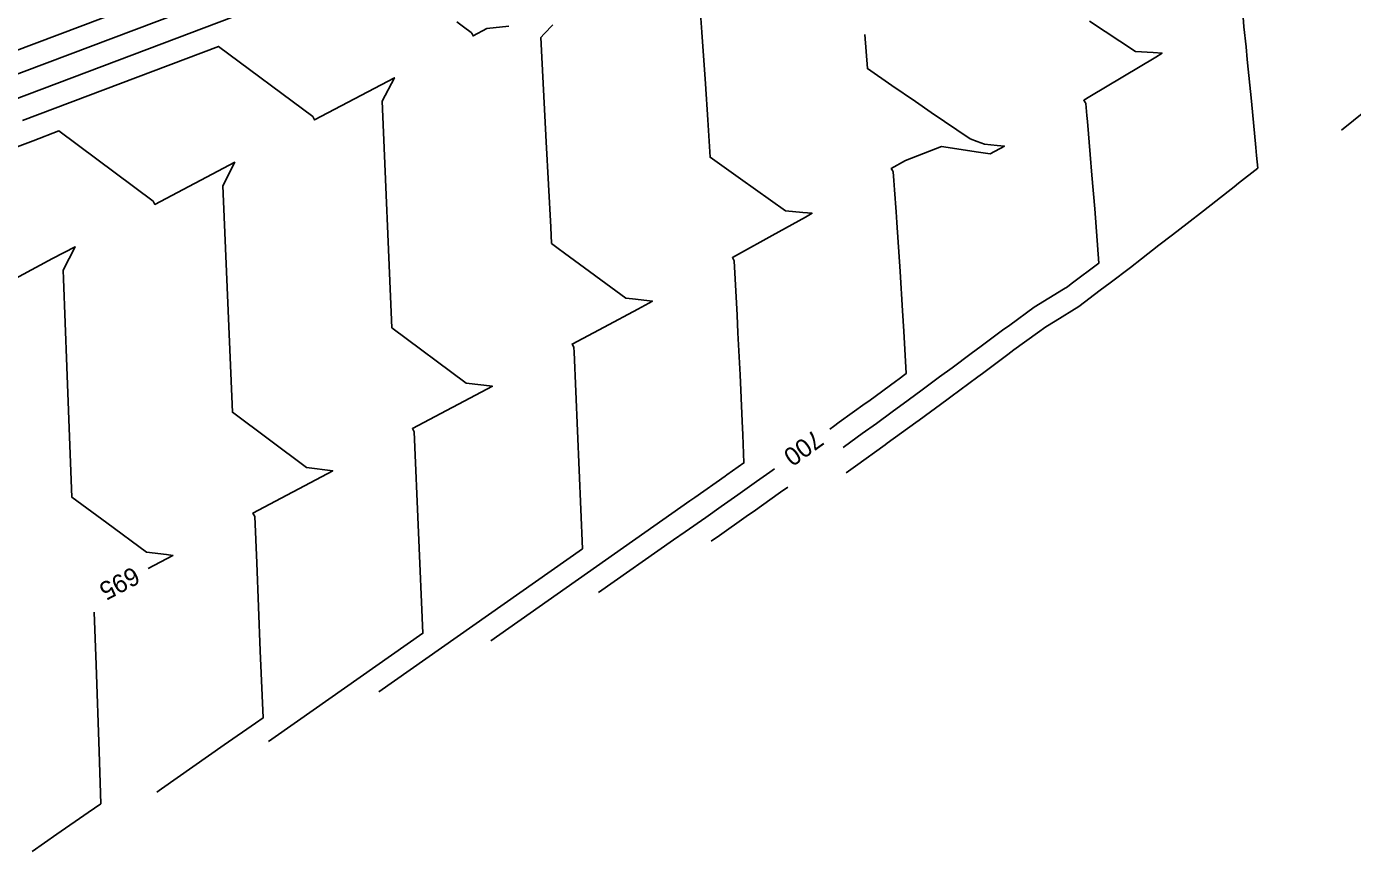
# Model space of a CAD drawing. Extents: x 1487507 to 1489130, y 497211 to 499439.
# Drawn here: x 1488049 to 1488223.8, y 498457.6 to 498566.4 of the extents above; entities that cross this region are included whole.
import ezdxf

# ---------------------------------------------------------------- set-up
doc = ezdxf.new("R2010")
doc.units = 0
for name, color, linetype in [('Prop CMT Ditch DDE', 7, 'Continuous'), ('Prop Drainage Ditch Flow Line', 7, 'Continuous'), ('Prop Drainage Structure Pipe Outlet Channel Detail CELL', 7, 'Continuous')]:
    doc.layers.add(name, color=color, linetype=linetype)

msp = doc.modelspace()

# ---------------------------------------------------------------- linework, layer by layer
at = {"layer": 'Prop CMT Ditch DDE'}
for points in [[(1488022.19, 498550.42), (1488026.78, 498552.19), (1488031.49, 498553.98), (1488036.2, 498555.77), (1488040.91, 498557.55), (1488045.62, 498559.34), (1488092.76, 498577.16), (1488093.19, 498577.32), (1488097.35, 498578.88), (1488097.69, 498579.01), (1488097.79, 498579.05)], [(1488094.17, 498574.51), (1488047.03, 498556.69)], [(1488137.54, 498572.49), (1488138.03, 498565.7), (1488138.48, 498558.89), (1488138.81, 498554.11), (1488139.11, 498549.2), (1488143.12, 498546.34), (1488149.05, 498542.14), (1488151.35, 498541.91), (1488152.54, 498541.8), (1488151.68, 498541.31), (1488147.27, 498538.86), (1488142.86, 498536.42), (1488142.04, 498535.97), (1488142.09, 498535.89), (1488142.28, 498535.53), (1488142.37, 498533.91), (1488142.41, 498533.14), (1488142.67, 498528.35), (1488142.78, 498526.04), (1488143.07, 498520.49), (1488143.33, 498514.39), (1488143.41, 498512.61), (1488143.56, 498508.89), (1488141.33, 498507.31), (1488141.11, 498507.16), (1488137.1, 498504.33), (1488136.45, 498503.87), (1488132.88, 498501.38), (1488110.17, 498485.43)], [(1488095.43, 498478.71), (1488122.27, 498497.56), (1488121.17, 498523.5), (1488121.14, 498524.12), (1488121.13, 498524.15), (1488120.91, 498524.56), (1488125.12, 498526.8), (1488129.57, 498529.18), (1488131.5, 498530.22), (1488128.85, 498530.52), (1488128.01, 498530.62), (1488119.92, 498536.56), (1488119.07, 498537.18), (1488118.19, 498537.84), (1488118.09, 498539.99), (1488117.5, 498551.24), (1488116.97, 498561.53), (1488116.78, 498564.97), (1488117.22, 498565.45), (1488118.37, 498566.67)], [(1488112.57, 498566.49), (1488109.68, 498566.18), (1488107.85, 498565.2), (1488107.72, 498565.45), (1488107.62, 498565.64), (1488106.6, 498566.4), (1488105.71, 498567.07)], [(1488189.12, 498567.13), (1488195.19, 498563.14), (1488197.51, 498563), (1488198.7, 498562.92), (1488197.86, 498562.41), (1488193.52, 498559.8), (1488189.18, 498557.2), (1488188.37, 498556.72), (1488188.58, 498556.37), (1488188.63, 498556.29), (1488188.77, 498554.68), (1488188.84, 498553.9), (1488189.22, 498549.55), (1488189.44, 498546.83), (1488189.81, 498542.39), (1488190.36, 498535.24), (1488190.34, 498535.23), (1488186.69, 498532.48), (1488186.22, 498532.11), (1488185.69, 498531.79), (1488181.85, 498529.42), (1488178.61, 498527.07), (1488177.67, 498526.39), (1488174.83, 498524.27), (1488173.53, 498523.3), (1488171, 498521.43), (1488169.37, 498520.22), (1488167.08, 498518.53), (1488165.2, 498517.16), (1488163.12, 498515.64), (1488161.02, 498514.1), (1488159.16, 498512.76), (1488156.82, 498511.06), (1488156.64, 498510.93)], [(1488209.37, 498567.65), (1488209.49, 498566.4), (1488209.77, 498563.76), (1488209.93, 498562.1), (1488210.48, 498556.61), (1488211.06, 498550.48), (1488211.16, 498549.44), (1488211.31, 498547.77), (1488208.77, 498545.76), (1488208.2, 498545.31), (1488207.39, 498544.68), (1488204.14, 498542.13), (1488201.99, 498540.46), (1488200.05, 498538.95), (1488198.28, 498537.58), (1488195.96, 498535.79), (1488194.51, 498534.67), (1488191.86, 498532.64), (1488190.55, 498531.65), (1488187.73, 498529.52), (1488184.62, 498527.6), (1488183.35, 498526.82), (1488182.28, 498526.04), (1488179.16, 498523.79), (1488178.36, 498523.19), (1488175.01, 498520.69), (1488174.39, 498520.24), (1488170.84, 498517.61), (1488170.31, 498517.21), (1488166.67, 498514.54), (1488166.24, 498514.22), (1488162.47, 498511.48), (1488162.19, 498511.27), (1488158.27, 498508.44), (1488157.06, 498507.56)], [(1488048.43, 498554.03), (1488074.27, 498563.81), (1488086.71, 498554.55), (1488086.95, 498554.11), (1488097.47, 498559.68), (1488095.88, 498556.57), (1488097.15, 498526.7), (1488106.92, 498519.42), (1488110.39, 498518.99), (1488099.86, 498513.42), (1488100.1, 498512.98), (1488101.23, 498486.42), (1488088.83, 498477.72), (1488084.7, 498474.82), (1488080.89, 498472.15)], [(1488222.36, 498552.77), (1488225.52, 498555.31)], [(1488030.68, 498544.12), (1488030.99, 498544.24), (1488035.7, 498546.03), (1488040.41, 498547.81), (1488045.12, 498549.6), (1488049.84, 498551.38), (1488053.23, 498552.67), (1488065.67, 498543.41), (1488065.91, 498542.97), (1488076.43, 498548.54), (1488074.84, 498545.44), (1488076.11, 498515.56), (1488085.88, 498508.29), (1488089.34, 498507.86), (1488078.82, 498502.28), (1488079.06, 498501.84), (1488079.32, 498495.69), (1488079.8, 498484.09), (1488080.16, 498475.27), (1488079.18, 498474.58), (1488075.05, 498471.69), (1488070.92, 498468.8), (1488066.79, 498465.92), (1488066.14, 498465.47)], [(1488149.33, 498505.69), (1488148.4, 498505.03), (1488144.76, 498502.44), (1488144.17, 498502.03), (1488140.02, 498499.11), (1488139.93, 498499.04), (1488139.25, 498498.56)]]:
    msp.add_lwpolyline(points, dxfattribs=at)
at = {"layer": 'Prop Drainage Ditch Flow Line'}
for points in [[(1488021.03, 498553.17), (1488025.37, 498554.84), (1488030.08, 498556.63), (1488034.79, 498558.42), (1488039.51, 498560.21), (1488044.22, 498561.99), (1488091.36, 498579.81), (1488092.2, 498580.13), (1488095.94, 498581.53), (1488096.69, 498581.82), (1488096.77, 498581.85)], [(1488159.51, 498565.38), (1488159.85, 498560.89), (1488163.08, 498558.65), (1488166.19, 498556.53), (1488168.27, 498555.1), (1488173.4, 498551.62), (1488174.3, 498551.28), (1488175.28, 498550.91), (1488176.93, 498550.76), (1488177.9, 498550.67), (1488176.01, 498549.65), (1488174.5, 498549.87), (1488169.62, 498550.6), (1488164.85, 498548.77), (1488162.99, 498547.71), (1488163.14, 498547.46), (1488163.24, 498547.28), (1488163.32, 498546.13), (1488163.41, 498544.89), (1488163.62, 498541.98), (1488163.71, 498540.57), (1488164.15, 498534.13), (1488164.46, 498528.93), (1488164.63, 498526.26), (1488164.95, 498520.67), (1488163.84, 498519.85), (1488163.74, 498519.77), (1488160.01, 498517.05), (1488159.56, 498516.73), (1488156.14, 498514.24), (1488155.38, 498513.69), (1488154.9, 498513.35)], [(1488065.03, 498494.98), (1488068.27, 498496.7), (1488067.41, 498496.8), (1488064.79, 498497.12), (1488059.54, 498500.99), (1488054.96, 498504.36), (1488054.74, 498510.05), (1488054.3, 498521.57), (1488053.84, 498533.14), (1488053.79, 498534.29), (1488055.38, 498537.4), (1488052.41, 498535.83), (1488047.99, 498533.49), (1488044.8, 498531.8), (1488044.56, 498532.24), (1488041.99, 498534.13), (1488032.73, 498540.95), (1488032.03, 498541.44), (1488031.91, 498541.4)], [(1488147.59, 498508.11), (1488146.97, 498507.66), (1488145.24, 498506.44), (1488142.75, 498504.67), (1488140.57, 498503.13), (1488138.52, 498501.69), (1488135.81, 498499.8), (1488134.28, 498498.73), (1488124.4, 498491.79)], [(1488049.72, 498457.65), (1488052.99, 498459.92), (1488057.12, 498462.8), (1488058.76, 498463.94), (1488058.54, 498470.82), (1488058.15, 498482.24), (1488057.9, 498489.21)]]:
    msp.add_lwpolyline(points, dxfattribs=at)

# ---------------------------------------------------------------- texts
at = {"layer": 'Prop Drainage Structure Pipe Outlet Channel Detail CELL'}
for s, rotation, p in [('700', 215.7588, (1488152.9, 498513.39)), ('695', 207.8997, (1488063.06, 498495.3))]:
    msp.add_text(s, height=2.4, rotation=rotation, dxfattribs=at).set_placement(p)

doc.saveas('drawing.dxf')
